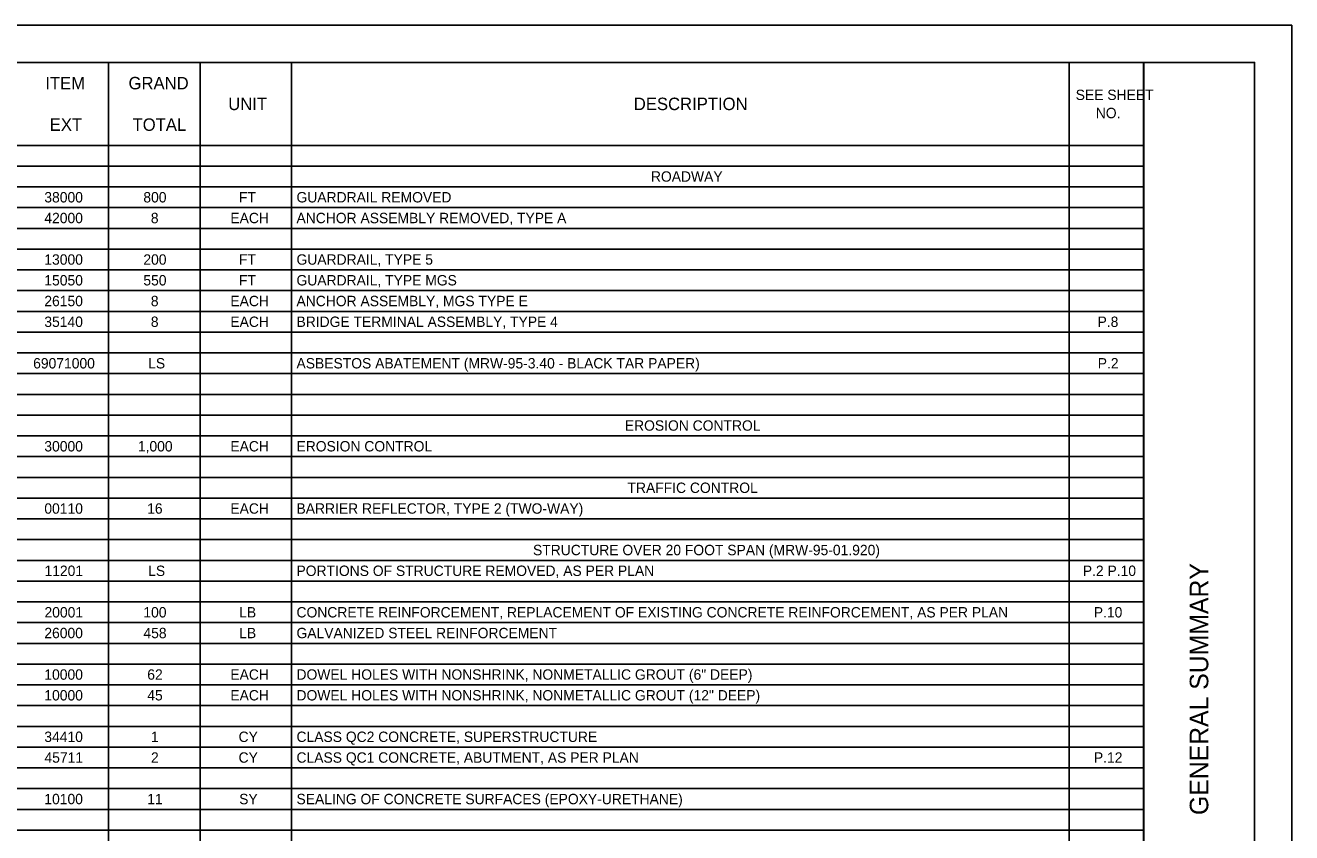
# Model space of a CAD drawing. Extents: x 0 to 34, y 0 to 22.
# Drawn here: x 16.91 to 34, y 11.11 to 22 of the extents above; entities that cross this region are included whole.
import ezdxf

# ---------------------------------------------------------------- set-up
doc = ezdxf.new("R2010")
doc.units = 0
for name, color, linetype in [('SH_Border', 7, 'Continuous'), ('SH_Cut_Line', 7, 'Continuous'), ('SH_Data', 7, 'Continuous'), ('SH_Text', 7, 'Continuous')]:
    doc.layers.add(name, color=color, linetype=linetype)

msp = doc.modelspace()

# ---------------------------------------------------------------- linework, layer by layer
at = {"layer": 'SH_Border'}
msp.add_line((32, 0.5), (32, 21.5), dxfattribs=at)
msp.add_lwpolyline([(1.5, 21.5), (33.5, 21.5), (33.5, 0.5), (1.5, 0.5)], close=True, dxfattribs=at)
at = {"layer": 'SH_Cut_Line'}
msp.add_lwpolyline([(0, 0), (34, 0), (34, 22), (0, 22)], close=True, dxfattribs=at)
at = {"layer": 'SH_Data'}
for p, q in [((1.5, 21.5), (32.004, 21.5)), ((18.036, 21.5), (18.036, 0.5)), ((19.272, 21.5), (19.272, 0.5)), ((20.507, 21.5), (20.507, 0.5)), ((30.999, 21.5), (30.999, 0.5)), ((32.004, 21.5), (32.004, 0.5)), ((1.5, 20.38), (32.004, 20.38)), ((1.5, 20.1), (32.004, 20.1)), ((1.5, 19.82), (32.004, 19.82)), ((1.5, 19.54), (32.004, 19.54)), ((1.5, 19.26), (32.004, 19.26)), ((1.5, 18.98), (32.004, 18.98)), ((1.5, 18.7), (32.004, 18.7)), ((1.5, 18.42), (32.004, 18.42)), ((1.5, 18.14), (32.004, 18.14)), ((1.5, 17.86), (32.004, 17.86)), ((1.5, 17.58), (32.004, 17.58)), ((1.5, 17.3), (32.004, 17.3)), ((1.5, 17.02), (32.004, 17.02)), ((1.5, 16.74), (32.004, 16.74)), ((1.5, 16.46), (32.004, 16.46)), ((1.5, 16.18), (32.004, 16.18)), ((1.5, 15.9), (32.004, 15.9)), ((1.5, 15.62), (32.004, 15.62)), ((1.5, 15.34), (32.004, 15.34)), ((1.5, 15.06), (32.004, 15.06)), ((1.5, 14.78), (32.004, 14.78)), ((1.5, 14.5), (32.004, 14.5)), ((1.5, 14.22), (32.004, 14.22)), ((1.5, 13.94), (32.004, 13.94)), ((1.5, 13.66), (32.004, 13.66)), ((1.5, 13.38), (32.004, 13.38)), ((1.5, 13.1), (32.004, 13.1)), ((1.5, 12.82), (32.004, 12.82)), ((1.5, 12.54), (32.004, 12.54)), ((1.5, 12.26), (32.004, 12.26)), ((1.5, 11.98), (32.004, 11.98)), ((1.5, 11.7), (32.004, 11.7)), ((1.5, 11.42), (32.004, 11.42)), ((1.5, 11.14), (32.004, 11.14))]:
    msp.add_line(p, q, dxfattribs=at)

# ---------------------------------------------------------------- texts
msp.add_text('GENERAL SUMMARY', height=0.25, rotation=90, dxfattribs=at).set_placement((32.875, 11.344))
at = {"layer": 'SH_Text'}
for s, height, p in [('ITEM', 0.168, (17.184, 21.136)), ('GRAND', 0.168, (18.307, 21.136)), ('UNIT', 0.168, (19.652, 20.856)), ('DESCRIPTION', 0.168, (25.124, 20.856)), ('SEE SHEET ', 0.14, (31.086, 20.992)), ('NO.', 0.14, (31.357, 20.747)), ('EXT', 0.168, (17.244, 20.576)), ('TOTAL', 0.168, (18.361, 20.576)), ('ROADWAY', 0.14, (25.355, 19.89)), ('38000', 0.14, (17.171, 19.61)), ('800', 0.14, (18.507, 19.61)), ('FT', 0.14, (19.797, 19.61)), ('GUARDRAIL REMOVED', 0.14, (20.573, 19.61)), ('42000', 0.14, (17.171, 19.33)), ('8', 0.14, (18.608, 19.33)), ('EACH', 0.14, (19.681, 19.33)), ('ANCHOR ASSEMBLY REMOVED, TYPE A', 0.14, (20.573, 19.33)), ('13000', 0.14, (17.171, 18.77)), ('200', 0.14, (18.507, 18.77)), ('FT', 0.14, (19.797, 18.77)), ('GUARDRAIL, TYPE 5', 0.14, (20.573, 18.77)), ('15050', 0.14, (17.171, 18.49)), ('550', 0.14, (18.507, 18.49)), ('FT', 0.14, (19.797, 18.49)), ('GUARDRAIL, TYPE MGS', 0.14, (20.573, 18.49)), ('26150', 0.14, (17.171, 18.21)), ('8', 0.14, (18.608, 18.21)), ('EACH', 0.14, (19.681, 18.21)), ('ANCHOR ASSEMBLY, MGS TYPE E', 0.14, (20.573, 18.21)), ('35140', 0.14, (17.171, 17.93)), ('8', 0.14, (18.608, 17.93)), ('EACH', 0.14, (19.681, 17.93)), ('BRIDGE TERMINAL ASSEMBLY, TYPE 4', 0.14, (20.573, 17.93)), ('P.8', 0.14, (31.381, 17.93)), ('69071000', 0.14, (17.02, 17.37)), ('LS', 0.14, (18.572, 17.37)), ('ASBESTOS ABATEMENT (MRW-95-3.40 - BLACK TAR PAPER)', 0.14, (20.573, 17.37)), ('P.2', 0.14, (31.383, 17.37)), ('EROSION CONTROL', 0.14, (25.003, 16.53)), ('30000', 0.14, (17.171, 16.25)), ('1,000', 0.14, (18.433, 16.25)), ('EACH', 0.14, (19.681, 16.25)), ('EROSION CONTROL', 0.14, (20.573, 16.25)), ('TRAFFIC CONTROL', 0.14, (25.039, 15.69)), ('00110', 0.14, (17.171, 15.41)), ('16', 0.14, (18.558, 15.41)), ('EACH', 0.14, (19.681, 15.41)), ('BARRIER REFLECTOR, TYPE 2 (TWO-WAY)', 0.14, (20.573, 15.41)), ('STRUCTURE OVER 20 FOOT SPAN (MRW-95-01.920)', 0.14, (23.764, 14.85)), ('11201', 0.14, (17.173, 14.57)), ('LS', 0.14, (18.572, 14.57)), ('PORTIONS OF STRUCTURE REMOVED, AS PER PLAN', 0.14, (20.573, 14.57)), ('P.2 P.10', 0.14, (31.182, 14.57)), ('20001', 0.14, (17.173, 14.01)), ('100', 0.14, (18.507, 14.01)), ('LB', 0.14, (19.8, 14.01)), ('CONCRETE REINFORCEMENT, REPLACEMENT OF EXISTING CONCRETE REINFORCEMENT, AS PER PLAN', 0.14, (20.573, 14.01)), ('P.10', 0.14, (31.33, 14.01)), ('26000', 0.14, (17.171, 13.73)), ('458', 0.14, (18.508, 13.73)), ('LB', 0.14, (19.8, 13.73)), ('GALVANIZED STEEL REINFORCEMENT', 0.14, (20.573, 13.73)), ('10000', 0.14, (17.171, 13.17)), ('62', 0.14, (18.56, 13.17)), ('EACH', 0.14, (19.681, 13.17)), ('DOWEL HOLES WITH NONSHRINK, NONMETALLIC GROUT (6" DEEP)', 0.14, (20.573, 13.17)), ('10000', 0.14, (17.171, 12.89)), ('45', 0.14, (18.56, 12.89)), ('EACH', 0.14, (19.681, 12.89)), ('DOWEL HOLES WITH NONSHRINK, NONMETALLIC GROUT (12" DEEP)', 0.14, (20.573, 12.89)), ('34410', 0.14, (17.171, 12.33)), ('1', 0.14, (18.61, 12.33)), ('CY', 0.14, (19.792, 12.33)), ('CLASS QC2 CONCRETE, SUPERSTRUCTURE', 0.14, (20.573, 12.33)), ('45711', 0.14, (17.173, 12.05)), ('2', 0.14, (18.61, 12.05)), ('CY', 0.14, (19.792, 12.05)), ('CLASS QC1 CONCRETE, ABUTMENT, AS PER PLAN', 0.14, (20.573, 12.05)), ('P.12', 0.14, (31.332, 12.05)), ('10100', 0.14, (17.171, 11.49)), ('11', 0.14, (18.559, 11.49)), ('SY', 0.14, (19.8, 11.49)), ('SEALING OF CONCRETE SURFACES (EPOXY-URETHANE)', 0.14, (20.573, 11.49))]:
    msp.add_text(s, height=height, dxfattribs=at).set_placement(p)

doc.saveas('drawing.dxf')
